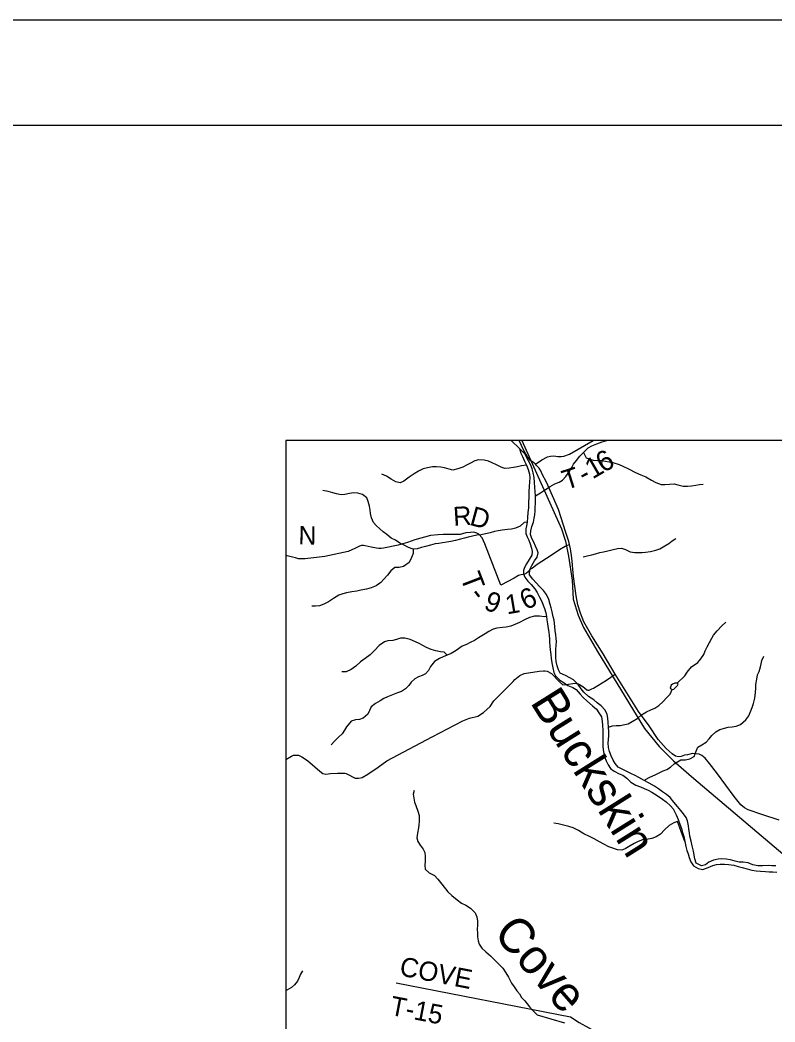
# Model space of a CAD drawing. Extents: x -139 to 835, y 0 to 440.
# Drawn here: x 348 to 419.7, y 344.8 to 440 of the extents above; entities that cross this region are included whole.
import ezdxf

# ---------------------------------------------------------------- set-up
doc = ezdxf.new("R2010")
doc.units = 0
for name, color, linetype in [('Default', 7, 'Continuous'), ('GM_X_Minor_Lake', 7, 'Continuous'), ('GM_X_Minor_River', 7, 'Continuous'), ('GM_X_Minor_River_Text', 7, 'Continuous'), ('GM_X_Rail_Line', 7, 'Continuous'), ('GM_X_State_Route', 7, 'Continuous'), ('GM_X_Township_Road', 7, 'Continuous'), ('GM_X_Township_Road_Text', 7, 'Continuous'), ('SH_Border', 7, 'Continuous'), ('SH_Cut_Line', 7, 'Continuous')]:
    doc.layers.add(name, color=color, linetype=linetype)

msp = doc.modelspace()

# ---------------------------------------------------------------- linework, layer by layer
at = {"layer": 'Default'}
msp.add_lwpolyline([(567.097, 400.079), (373.24, 400.079), (373.24, 306.128)], dxfattribs=at)
at = {"layer": 'GM_X_Minor_Lake'}
for points in [[(409.951, 376.426), (410.095, 376.461), (410.332, 376.663), (410.45, 376.806), (410.517, 376.913), (410.4, 377.023), (410.205, 377.024), (409.969, 376.93), (409.838, 376.835), (409.757, 376.56)], [(409.757, 376.56), (409.951, 376.426)]]:
    msp.add_lwpolyline(points, dxfattribs=at)
at = {"layer": 'GM_X_Minor_River'}
msp.add_line((394.659, 400.079), (395.449, 399.311), dxfattribs=at)
for points in [[(396.948, 394.823), (397.433, 395.107), (397.905, 395.403), (398.351, 395.711), (398.784, 395.959), (399.19, 396.111), (399.53, 396.3), (399.847, 396.657), (400.164, 397.099), (400.416, 397.505), (400.549, 397.815), (400.852, 398.161), (401.182, 398.566), (401.499, 398.935), (401.959, 399.375), (402.3, 399.552), (402.772, 399.764), (403.295, 399.927), (403.72, 400.079)], [(395.449, 399.311), (395.565, 398.856), (395.719, 398.543), (395.923, 398.109), (396.115, 397.723), (396.255, 397.326), (396.381, 396.881), (396.404, 396.557), (396.399, 396.113), (396.356, 395.717), (396.325, 395.189), (396.307, 394.685), (396.29, 394.205), (396.285, 393.677), (396.241, 393.234), (396.198, 392.754), (396.154, 392.31), (396.086, 391.975), (396.031, 391.675), (396.04, 391.243), (396.154, 390.918), (396.307, 390.593), (396.447, 390.256), (396.574, 389.846), (396.623, 389.522), (396.607, 389.174), (396.355, 388.756), (396.103, 388.35), (395.904, 388.004), (395.823, 387.705), (395.82, 387.405), (395.935, 387.08), (396.231, 386.717), (396.528, 386.402), (396.889, 385.991), (397.12, 385.617), (397.337, 385.183), (397.568, 384.784), (397.682, 384.435), (397.796, 384.122), (397.936, 383.701), (397.997, 383.364), (398.046, 383.04), (398.095, 382.655), (398.156, 382.199), (398.218, 381.85), (398.241, 381.55), (398.277, 381.213), (398.3, 380.913), (398.322, 380.541), (398.358, 380.192), (398.406, 379.736), (398.441, 379.352), (398.515, 378.943), (398.589, 378.474), (398.702, 378.029), (398.855, 377.703), (399.281, 377.303), (399.67, 377.036), (400.033, 376.804), (400.487, 376.608), (400.824, 376.413), (401.211, 375.989), (401.495, 375.662), (401.843, 375.347), (402.373, 374.874), (402.735, 374.547), (402.967, 374.209), (403.21, 373.822), (403.297, 373.389), (403.333, 373.029), (403.354, 372.525), (403.345, 371.576), (403.352, 370.976), (403.4, 370.496), (403.499, 370.027), (403.665, 369.653), (403.857, 369.267), (404.075, 368.917), (404.412, 368.674), (404.918, 368.405), (405.255, 368.27), (405.631, 367.991), (406.005, 367.603), (406.472, 367.335), (406.939, 367.175), (407.29, 367.003), (407.667, 366.868), (408.017, 366.673), (408.509, 366.344), (409.028, 366.004), (409.377, 365.76), (409.765, 365.373), (410.036, 365.071), (410.317, 364.528), (410.508, 364.058), (410.661, 363.625), (410.839, 363.215), (410.927, 362.842), (411.053, 362.445), (411.153, 361.976)], [(411.481, 363.473), (411.394, 363.954), (411.254, 364.268), (411.022, 364.606), (410.765, 364.92), (410.429, 365.295), (410.107, 365.706), (409.759, 366.153), (409.397, 366.444), (409.008, 366.712), (408.646, 366.979), (408.244, 367.235), (407.738, 367.528), (407.284, 367.772), (406.779, 368.052), (406.415, 368.248), (406.013, 368.455), (405.637, 368.639), (405.299, 368.774), (404.793, 369.043), (404.51, 369.381), (404.331, 369.707), (404.139, 370.105), (404, 370.538), (403.899, 370.923), (403.864, 371.344), (403.88, 371.644), (403.91, 372.051), (403.914, 372.423), (403.892, 372.832), (403.844, 373.276), (403.822, 373.697), (403.76, 374.045), (403.582, 374.467), (403.182, 374.879), (402.819, 375.158), (402.483, 375.425), (401.991, 375.766), (401.551, 376.154), (401.307, 376.492), (400.998, 376.879), (400.559, 377.339), (400.209, 377.535), (399.794, 377.743), (399.314, 377.975), (399.135, 378.289), (399.008, 378.674), (398.934, 379.071), (398.885, 379.455), (398.876, 379.876), (398.892, 380.187), (398.923, 380.631), (398.952, 380.931), (398.929, 381.279), (398.893, 381.604), (398.832, 382.012), (398.783, 382.373), (398.747, 382.709), (398.724, 383.01), (398.649, 383.322), (398.523, 383.804), (398.436, 384.176), (398.347, 384.501), (398.235, 384.982), (398.004, 385.429), (397.721, 385.815), (397.321, 386.203), (397.024, 386.542), (396.715, 386.893), (396.38, 387.316), (396.411, 387.808), (396.61, 388.202), (396.875, 388.631), (397.126, 388.977), (397.195, 389.385), (397.107, 389.685), (396.967, 390.023), (396.801, 390.42), (396.622, 390.77), (396.495, 391.155), (396.512, 391.503), (396.607, 391.886), (396.754, 392.317), (396.836, 392.688), (396.878, 393.012), (396.908, 393.384), (396.924, 393.708), (396.941, 394.079), (396.958, 394.499), (396.948, 394.823), (396.912, 395.196), (396.877, 395.64), (396.855, 396.072), (396.821, 396.553), (396.747, 397.009), (396.633, 397.383), (396.506, 397.732), (396.301, 398.13), (396.096, 398.491), (395.956, 398.805), (395.449, 399.311)], [(401.499, 398.935), (401.781, 398.416), (402.444, 398.206), (402.887, 398.179), (403.213, 398.152), (403.603, 398.112), (404.293, 397.986), (404.904, 397.801), (405.255, 397.618), (405.787, 397.361), (406.449, 397.043), (406.968, 396.81), (407.436, 396.602), (407.981, 396.309), (408.383, 396.078), (408.89, 395.881), (409.229, 395.878), (409.673, 395.934), (410.13, 395.943), (410.468, 395.868), (410.976, 395.743), (411.393, 395.74), (411.785, 395.76), (412.19, 395.829), (412.529, 395.874), (412.882, 395.907)], [(396.115, 397.723), (395.632, 397.668), (395.24, 397.575), (394.874, 397.506), (394.469, 397.426), (394.013, 397.418), (393.623, 397.566), (393.247, 397.749), (392.844, 397.957), (392.494, 398.092), (392.09, 398.192), (391.543, 398.22), (391.203, 398.14), (390.771, 397.903), (390.404, 397.715), (390.063, 397.538), (389.592, 397.362), (389.109, 397.258), (388.77, 397.333), (388.315, 397.457), (387.977, 397.52), (387.56, 397.56), (387.169, 397.552), (386.711, 397.484), (386.28, 397.38), (385.848, 397.167), (385.428, 396.907), (384.969, 396.587), (384.456, 396.208), (384.103, 396.055), (383.673, 396.143), (383.258, 396.398), (382.817, 396.666), (382.363, 396.862)], [(396.154, 392.31), (395.867, 392.265), (395.499, 391.944), (395.041, 391.745), (394.675, 391.64), (394.283, 391.619), (393.774, 391.54), (393.396, 391.496), (393.056, 391.415), (392.65, 391.286), (392.206, 391.194), (391.801, 391.102), (391.384, 391.07), (390.966, 390.99), (390.574, 390.885), (390.221, 390.804), (389.816, 390.7), (389.345, 390.584), (388.901, 390.468), (388.548, 390.412), (388.117, 390.344), (387.778, 390.299), (387.439, 390.242), (386.994, 390.126), (386.511, 390.01), (386.118, 389.893), (385.713, 389.777), (385.334, 389.744), (384.893, 389.904), (384.477, 390.124), (384.075, 390.308), (383.647, 390.587), (383.232, 390.807), (382.831, 391.135), (382.494, 391.378), (382.184, 391.68), (381.821, 391.983), (381.576, 392.285), (381.385, 392.731), (381.284, 393.14), (381.235, 393.452), (381.174, 393.837), (381.06, 394.258), (380.946, 394.607), (380.519, 394.934), (380.063, 395.058), (379.672, 395.086), (379.28, 395.041), (378.836, 394.925), (378.509, 394.915), (378.067, 395.003), (377.702, 395.09), (377.26, 395.214), (376.752, 395.314)], [(401.481, 389.033), (401.873, 389.114), (402.291, 389.194), (402.657, 389.299), (403.076, 389.427), (403.415, 389.496), (403.833, 389.6), (404.33, 389.728), (404.735, 389.808), (405.127, 389.841), (405.504, 389.717), (405.958, 389.497), (406.375, 389.445), (406.714, 389.431), (407.092, 389.439), (407.418, 389.472), (407.875, 389.528), (408.385, 389.644), (408.778, 389.772), (409.25, 390.068), (409.605, 390.293), (409.946, 390.531), (410.274, 390.744)], [(385.334, 389.744), (385.344, 389.324), (385.17, 388.954), (384.944, 388.476), (384.419, 388.085), (384.014, 388.016), (383.584, 388.008), (383.202, 387.688), (382.886, 387.282), (382.543, 386.901), (382.253, 386.58), (381.807, 386.26), (381.348, 386.084), (380.891, 385.956), (380.368, 385.853), (379.976, 385.772), (379.519, 385.692), (379.009, 385.6), (378.669, 385.507), (378.276, 385.367), (377.778, 385.059), (377.279, 384.739), (376.859, 384.515), (376.441, 384.374), (376.049, 384.318), (375.696, 384.321)], [(397.997, 383.364), (397.815, 383.33), (397.346, 383.37), (396.851, 383.387), (396.393, 383.271), (395.896, 383.024), (395.45, 382.788), (394.979, 382.588), (394.612, 382.424), (394.181, 382.332), (393.816, 382.311), (393.294, 382.256), (392.941, 382.139), (392.535, 381.939), (392.168, 381.702), (391.525, 381.312), (391.158, 381.076), (390.752, 380.887), (390.412, 380.698), (389.98, 380.534), (389.428, 380.131), (388.956, 379.836), (388.564, 379.683), (388.184, 379.531), (387.844, 379.366), (387.359, 379.07), (386.989, 378.618), (386.777, 378.224), (386.513, 377.902), (386.186, 377.749), (385.845, 377.62), (385.478, 377.42), (385.15, 377.111), (384.938, 376.788), (384.622, 376.479), (384.215, 376.219), (383.862, 376.114), (383.365, 375.915), (382.881, 375.727), (382.54, 375.55), (382.186, 375.337), (381.753, 375.101), (381.333, 374.769), (381.199, 374.41), (381.026, 374.087), (380.579, 373.683), (380.226, 373.566), (379.847, 373.522), (379.442, 373.405), (379.006, 372.869), (378.807, 372.547), (378.582, 372.201), (378.253, 371.879), (377.871, 371.499), (377.555, 371.177)], [(410.4, 377.023), (411.138, 377.712), (411.363, 378.071), (411.785, 378.583), (412.363, 378.974), (412.653, 379.32), (412.932, 379.738), (413.078, 380.084), (413.265, 380.467), (413.478, 380.897), (413.703, 381.279), (413.876, 381.59), (414.219, 381.995), (414.667, 382.46), (415.023, 382.805)], [(388.564, 379.683), (388.28, 379.974), (387.941, 380.001), (387.499, 380.089), (387.057, 380.225), (386.615, 380.421), (386.239, 380.593), (385.902, 380.8), (385.564, 380.935), (385.045, 381.167), (384.537, 381.304), (384.146, 381.296), (383.741, 381.167), (383.401, 381.074), (382.944, 381.054), (382.604, 380.961), (382.092, 380.582), (381.657, 380.13), (381.236, 379.725), (380.789, 379.369), (380.317, 379.061), (379.883, 378.645), (379.436, 378.313), (378.977, 378.101), (378.547, 378.081)], [(407.284, 367.772), (407.403, 367.867), (407.809, 368.079), (408.307, 368.327), (409.067, 368.68), (409.446, 368.833), (409.788, 369.046), (410.117, 369.343), (410.772, 369.733), (411.203, 369.754), (411.608, 369.822), (412.015, 370.059), (412.215, 370.561), (412.389, 370.956), (412.743, 371.157), (413.163, 371.417), (413.44, 371.727), (413.717, 372.061), (414.086, 372.394), (414.466, 372.606), (414.898, 372.759), (415.264, 372.84), (415.63, 372.873), (416.022, 372.942), (416.428, 373.094), (416.929, 373.546), (417.206, 373.928), (417.353, 374.239), (417.527, 374.718), (417.648, 375.089), (417.797, 375.58), (417.854, 376.119), (417.872, 376.551), (417.888, 376.887), (417.971, 377.415), (418.054, 377.798), (418.2, 378.133), (418.335, 378.564), (418.403, 378.864), (418.445, 379.163), (418.658, 379.594)], [(403.892, 372.832), (404.271, 372.96), (404.623, 372.993), (404.989, 373.014), (405.433, 373.082), (405.759, 373.163), (406.152, 373.375), (406.677, 373.683), (407.033, 374.028), (407.492, 374.312), (407.898, 374.476), (408.304, 374.652), (408.658, 374.901), (409.066, 375.234), (409.435, 375.651), (409.738, 375.972), (409.951, 376.426)], [(385.443, 366.824), (385.348, 366.476), (385.384, 366.092), (385.471, 365.707), (385.573, 365.394), (385.763, 364.876), (385.889, 364.443), (385.91, 363.891), (385.868, 363.579), (385.839, 363.28), (385.743, 362.788), (385.674, 362.333), (385.775, 361.984), (386.006, 361.646), (386.289, 361.259), (386.429, 360.934), (386.478, 360.55), (386.46, 360.094), (386.444, 359.734), (386.479, 359.361), (386.867, 359.01), (387.347, 358.753), (387.682, 358.39), (388.056, 357.919), (388.635, 357.193), (388.997, 356.866), (389.501, 356.441), (389.941, 356.137), (390.33, 355.929), (390.784, 355.661), (391.223, 355.2), (391.376, 354.839), (391.437, 354.43), (391.446, 354.022), (391.429, 353.662), (391.439, 353.29), (391.461, 352.918), (391.51, 352.545), (391.611, 352.22), (391.855, 351.846), (392.242, 351.494), (392.682, 351.118), (393.03, 350.778), (393.43, 350.366), (393.843, 349.954), (394.126, 349.52), (394.382, 349.085), (394.676, 348.518), (394.934, 348.168), (395.191, 347.805), (395.436, 347.503), (395.641, 347.153), (395.95, 346.838), (396.401, 346.281), (396.685, 345.978), (397.123, 345.53), (399.696, 344.759)], [(411.153, 361.976), (410.441, 363.891), (410.101, 363.75), (409.642, 363.502), (409.221, 363.085), (408.813, 362.693), (408.419, 362.432), (408.013, 362.256), (407.504, 362.176), (407.112, 362.156), (406.706, 361.979), (406.313, 361.803), (405.946, 361.578), (405.474, 361.295), (405.147, 361.153), (404.756, 361.205), (404.314, 361.341), (403.912, 361.489), (403.432, 361.733), (403.03, 361.953), (402.537, 362.222), (402.07, 362.454), (401.538, 362.699), (401.046, 363.016), (400.527, 363.273), (400.111, 363.409), (399.617, 363.546), (399.097, 363.659), (398.707, 363.734)], [(419.795, 359.659), (419.403, 359.686), (419.077, 359.689), (418.529, 359.657), (418.085, 359.673), (417.603, 359.761), (417.161, 359.957), (416.679, 360.033), (416.287, 360.012), (415.91, 360.111), (415.481, 360.247), (415.064, 360.31), (414.633, 360.326), (414.294, 360.293), (413.862, 360.224), (413.417, 360.012), (413.088, 359.775), (412.709, 359.67), (412.216, 359.938), (412.102, 360.335), (411.953, 361.057), (411.841, 361.586), (411.728, 362.019), (411.628, 362.476), (411.579, 362.813), (411.517, 363.149), (411.481, 363.473)], [(411.153, 361.976), (411.24, 361.507), (411.341, 361.134), (411.442, 360.809), (411.543, 360.46), (411.708, 360.051), (411.952, 359.665), (412.393, 359.409), (412.836, 359.321), (413.347, 359.52), (413.792, 359.709), (414.158, 359.802), (414.498, 359.823), (414.902, 359.819), (415.294, 359.804), (415.789, 359.74), (416.218, 359.616), (416.583, 359.517), (417.064, 359.381), (417.494, 359.27), (417.911, 359.194), (418.315, 359.155), (418.797, 359.127), (419.163, 359.112), (419.515, 359.109), (419.867, 359.071)], [(374.835, 349.689), (374.63, 349.386), (374.508, 349.072), (374.35, 348.71), (374.073, 348.373), (373.762, 348.13), (373.343, 347.865), (373.24, 347.802)]]:
    msp.add_lwpolyline(points, dxfattribs=at)
at = {"layer": 'GM_X_Rail_Line'}
msp.add_lwpolyline([(395.652, 400.079), (399.415, 391.692), (399.8, 390.495), (400.096, 389.074), (400.426, 386.818), (400.526, 385.009), (401.002, 383.465), (401.506, 382.312), (402.853, 380.012), (407.3, 372.714), (408.705, 371.009), (410.068, 369.65), (412.003, 367.98), (426.013, 356.104), (434.107, 349.279), (435.89, 348.177), (437.988, 347.404), (441.359, 346.369), (443.681, 345.681), (444.906, 345.179), (445.837, 344.639)], dxfattribs=at)
at = {"layer": 'GM_X_State_Route'}
msp.add_lwpolyline([(420.095, 364.014), (418.468, 364.554), (417.141, 364.996), (416.817, 365.178), (416.467, 365.469), (415.821, 366.254), (414.248, 368.403), (413.487, 369.381), (413.074, 369.901), (412.75, 370.144), (412.503, 370.266), (412.204, 370.316), (411.878, 370.342), (411.407, 370.226), (411.107, 370.169), (410.793, 370.063), (410.532, 370.029), (410.246, 370.091), (409.922, 370.298), (409.365, 370.819), (408.616, 371.665), (407.741, 372.96), (406.733, 374.329), (404.51, 377.866), (403.377, 379.821), (402.318, 381.527), (401.562, 382.859), (401.215, 383.663), (400.988, 384.454), (400.807, 385.314), (400.58, 387.158), (400.403, 388.932), (400.271, 389.773), (400.194, 390.189), (400.126, 390.464), (400.008, 390.867), (399.85, 391.325), (399.128, 393.509), (397.99, 396.111), (397.579, 396.883), (397.451, 397.184), (397.297, 397.425), (397.064, 397.703), (396.943, 397.812), (396.792, 397.946), (396.482, 398.164), (396.185, 398.527), (395.851, 399.13), (395.397, 400.079)], dxfattribs=at)
at = {"layer": 'GM_X_Township_Road'}
for points in [[(396.943, 397.812), (397.543, 398.24), (398.092, 398.513), (398.379, 398.583), (398.692, 398.606), (399.07, 398.555), (399.383, 398.541), (399.656, 398.564), (400.179, 398.777), (402.433, 400.079)], [(400.194, 390.189), (399.759, 389.989), (399.226, 389.67), (398.428, 389.158), (397.119, 388.278), (396.661, 387.957), (396.491, 387.862), (396.4, 387.742), (396.268, 387.587), (396.111, 387.456), (395.889, 387.349), (395.589, 387.315), (395.341, 387.257), (394.923, 387.007), (393.667, 386.331), (392.152, 390.242), (391.895, 390.808), (391.584, 391.158), (391.389, 391.255), (391.09, 391.353), (390.79, 391.343), (390.347, 391.298), (389.785, 391.145), (389.121, 391.137), (388.169, 391.143), (387.713, 391.11), (386.995, 391.042), (385.507, 390.619), (384.802, 390.383), (383.901, 390.124), (382.53, 389.844), (382.308, 389.821), (382.087, 389.823), (381.839, 389.848), (381.357, 389.947), (380.771, 390.071), (380.602, 390.084), (380.432, 390.085), (380.223, 390.038), (379.792, 389.812), (379.504, 389.67), (379.164, 389.54), (376.931, 389.06), (375.078, 388.842), (374.765, 388.832), (374.439, 388.833), (374.152, 388.919), (373.866, 388.993), (373.358, 389.115), (373.24, 389.129)], [(373.24, 369.774), (373.789, 370.101), (373.963, 370.169), (374.168, 370.186), (374.441, 370.169), (374.75, 370.027), (375.306, 369.664), (376.465, 368.67), (376.767, 368.433), (377.052, 368.393), (377.489, 368.432), (378.14, 368.484), (378.855, 368.48), (378.982, 368.449), (379.112, 368.387), (379.281, 368.277), (379.56, 368.11), (379.829, 368.011), (379.943, 367.999), (380.13, 368.001), (380.319, 368.024), (380.476, 368.075), (381.042, 368.379), (382.003, 369.042), (382.823, 369.638), (387.145, 371.928), (390.068, 373.453), (390.701, 373.683), (391.474, 373.892), (392.024, 374.227), (392.661, 374.801), (392.998, 375.333), (394.821, 377.176), (395, 377.378), (395.466, 377.74), (395.869, 377.942), (397.301, 378.172), (397.715, 378.192), (397.857, 378.186), (398.073, 378.145), (398.466, 377.926), (399.221, 377.135), (399.55, 376.868), (399.892, 376.889), (400.702, 377.035), (400.997, 376.952), (401.122, 376.892), (401.444, 376.703), (401.84, 376.402), (401.878, 376.382), (401.941, 376.367), (402.057, 376.364), (402.317, 376.467), (402.48, 376.537), (403.705, 377.296), (404.51, 377.866)], [(383.712, 348.563), (400.286, 345.344), (401.118, 344.807), (402.94, 343.765), (403.191, 343.675)]]:
    msp.add_lwpolyline(points, dxfattribs=at)
at = {"layer": 'SH_Border'}
msp.add_lwpolyline([(30, 430), (670, 430), (670, 10), (30, 10)], close=True, dxfattribs=at)
at = {"layer": 'SH_Cut_Line'}
for points in [[(0, 0), (680, 0), (680, 440), (0, 440)], [(607.596, 213.413), (607.596, 400.079), (373.24, 400.079), (373.24, 228.621), (390.412, 227.867), (402.968, 227.036), (407.389, 226.858), (433.728, 225.419), (479.461, 222.215), (494.743, 221.147), (512.652, 220.106), (533.705, 218.461), (553.865, 217.083)]]:
    msp.add_lwpolyline(points, close=True, dxfattribs=at)

# ---------------------------------------------------------------- texts
at = {"layer": 'GM_X_Minor_River_Text'}
for s, rotation, p in [('Buckskin', 302.07199, (396.396, 375.212)), ('Cove', 311.28125, (392.85, 353.192))]:
    msp.add_text(s, height=3.3078, rotation=rotation, dxfattribs=at).set_placement(p)
at = {"layer": 'GM_X_Township_Road_Text'}
for s, height, rotation, p in [('6', 1.935, 30.41279, (403.395, 396.954)), ('1', 1.934, 30.1828, (402.369, 396.357)), ('T', 1.861, 17.50712, (399.835, 395.359)), ('-', 1.92, 27.42088, (401.576, 395.943)), ('R', 1.8, 3.65989, (389.189, 391.949)), ('D', 1.848, 344.7407, (390.61, 392.07)), ('N', 1.752, 358.93517, (374.428, 390.201)), ('T', 1.973, 291.04215, (389.773, 387.109)), ('-', 1.985, 307.99556, (390.538, 385.353)), ('9', 1.879, 339.66445, (391.942, 384.078)), ('1', 1.819, 9.53706, (394.245, 383.553)), ('6', 1.904, 24.64153, (396.002, 383.927)), ('COVE', 1.8252, 349.00899, (383.951, 349.279)), ('T-15', 1.8242, 349.22035, (383.043, 345.534))]:
    msp.add_text(s, height=height, rotation=rotation, dxfattribs=at).set_placement(p)

doc.saveas('drawing.dxf')
